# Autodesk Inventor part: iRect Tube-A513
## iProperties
Author: Rennick
Shininess: 60.0
PropertySet Name: _Private Model Information
Created: 2000-10
Part Number: iRect Tube-A513
Material: Steel, Mild
Document SubType Name: Modeling
Designer: Rennick
Description: 5 X 2 X 1/8in
Control State: 0
Master: False
Checked Out: False
PropertySet Name: Design Tracking Control
Density: 7.86
Volumn: 54.709238110235525
Area: 882.7334904367938
PropertySet Name: Model Information
